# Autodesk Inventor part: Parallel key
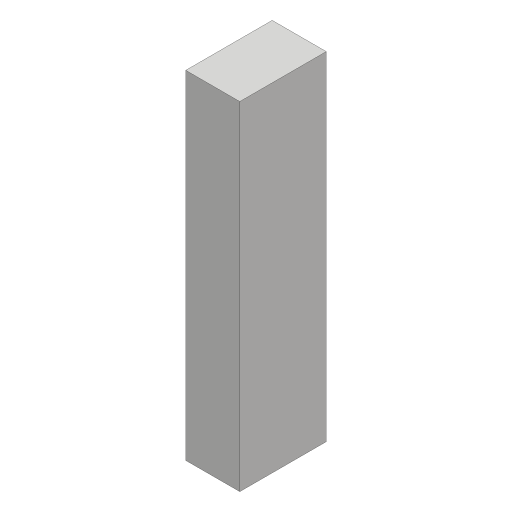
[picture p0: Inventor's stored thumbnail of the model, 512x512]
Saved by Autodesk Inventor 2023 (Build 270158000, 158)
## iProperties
Created: 2016-05
Part Number: Parallel key
Material: Generic
Document SubType Name: Modeling
Designer: CADCIM
Density: 1 g/cm^3
Appearance: Default
Author: CADCIM
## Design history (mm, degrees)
sketch "Sketch1"
  geometry: L1 (0, 0)-(16, 0); L2 (16, 0)-(16, -62.5); L3 (16, -62.5)-(0, -62.5); L4 (0, -62.5)-(0, 0)
  constraints: 8 end point, 2 parallel, 1 horizontal, 1 perpendicular
  dimensions: "d0" = 62.5 distance of L3.end L1.start; "d1" = 16 distance of L2.end L3.end
extrude "Extrusion1" new body sketch "Sketch1" distance "d2" = 10; taper "d3" = 0 deg
body "Solid1"
